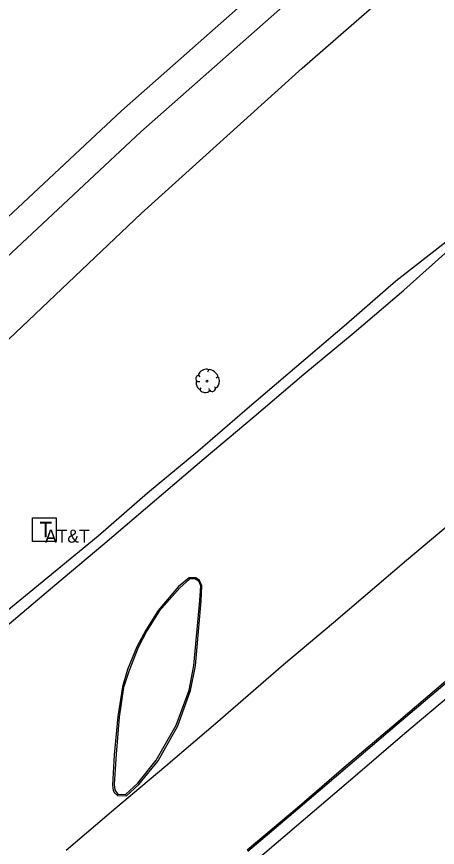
# Model space of a CAD drawing. Extents: x 1042086 to 1119166, y 1916606 to 1927565.
# Drawn here: x 1043115.4 to 1043276.4, y 1926533.5 to 1926851.6 of the extents above; entities that cross this region are included whole.
import ezdxf

# ---------------------------------------------------------------- set-up
doc = ezdxf.new("R2010")
doc.units = 0
for name, color, linetype in [('R_No Plot', 7, 'Continuous'), ('S_CURB', 7, 'Continuous'), ('S_EDGE_CONCRETE', 7, 'Continuous'), ('S_EDGE_PAVEMENT', 7, 'Continuous'), ('S_SHOULDER', 7, 'Continuous'), ('S_SIDEWALK', 7, 'Continuous'), ('S_TELEPHONE_UTILITIES', 7, 'Continuous'), ('S_TELEPHONE_UTILITIES_ANNOT', 7, 'Continuous'), ('S_TREE', 7, 'Continuous')]:
    doc.layers.add(name, color=color, linetype=linetype)

msp = doc.modelspace()

# ---------------------------------------------------------------- linework, layer by layer
at = {"layer": 'R_No Plot'}
for points in [[(1044190.35, 1927564.54), (1043981.84, 1927438.75), (1043847.5, 1927351.11), (1043782.09, 1927308.44), (1043697.07, 1927249.19), (1043570.31, 1927157.92), (1043487.46, 1927093.8), (1043395.3, 1927021.04), (1043346.81, 1926980.95), (1043282.61, 1926927.86), (1043155.48, 1926815.57), (1043010.71, 1926680.15), (1042651.83, 1926335.68), (1042368.92, 1926064.14), (1042086.02, 1925792.6)], [(1044196.03, 1927555.13), (1043987.69, 1927429.43), (1043853.51, 1927341.9), (1043788.24, 1927299.32), (1043703.43, 1927240.21), (1043576.89, 1927149.1), (1043494.23, 1927085.13), (1043402.21, 1927012.49), (1043353.82, 1926972.48), (1043289.76, 1926919.5), (1043162.88, 1926807.43), (1043018.28, 1926672.16), (1042659.44, 1926327.74), (1042376.54, 1926056.21), (1042093.64, 1925784.67)], [(1042478.4, 1926119.04), (1042593.51, 1926230.8), (1042805.67, 1926436.78), (1043162.99, 1926776.23), (1043224.64, 1926831.91), (1043251.28, 1926855.08), (1043316.64, 1926911.14), (1043414.38, 1926992.32), (1043498.45, 1927058.67), (1043606.9, 1927141.54), (1043742.89, 1927238.47), (1043809.93, 1927284.87), (1043730.4, 1927218.11), (1043687.56, 1927181.41)]]:
    msp.add_lwpolyline(points, dxfattribs=at)
at = {"layer": 'S_CURB'}
msp.add_lwpolyline([(1043203.91, 1926532.06), (1043222.97, 1926548.25), (1043242.02, 1926564.43), (1043261.02, 1926580.68), (1043280.9, 1926597.45), (1043299.84, 1926613.77), (1043313.23, 1926625.02), (1043315.83, 1926627.5), (1043317.07, 1926628.88), (1043319.73, 1926653.81), (1043320.19, 1926657.43), (1043321.03, 1926661.98), (1043324.28, 1926666.15)], dxfattribs=at)
msp.add_lwpolyline([(1043154.15, 1926553.83), (1043156.99, 1926553.69), (1043161.69, 1926558.01), (1043168.83, 1926566.88), (1043176.36, 1926580.23), (1043181.35, 1926593.72), (1043183.17, 1926603.09), (1043185.49, 1926627.97), (1043185.83, 1926633.66), (1043185.06, 1926635.38), (1043183.61, 1926636.35), (1043181.54, 1926636.17), (1043177.81, 1926632.9), (1043169.97, 1926623.94), (1043165.24, 1926616.36), (1043161.85, 1926610), (1043158.38, 1926601.22), (1043156.32, 1926594.67), (1043154.58, 1926583.34), (1043153.52, 1926569.12), (1043152.66, 1926557.67), (1043152.96, 1926555.49), (1043153.54, 1926554.55)], close=True, dxfattribs=at)
at = {"layer": 'S_EDGE_CONCRETE'}
msp.add_lwpolyline([(1042911.59, 1926420.57), (1042897.9, 1926435.96), (1042900.77, 1926438.95), (1042919.78, 1926455.34), (1042939.53, 1926471.89), (1042958.48, 1926488.19), (1042977.65, 1926504.25), (1042996.58, 1926520.57), (1043015.53, 1926536.87), (1043034.78, 1926552.83), (1043053.68, 1926569.19), (1043072.77, 1926585.33), (1043091.84, 1926601.49), (1043110.9, 1926617.67), (1043129.98, 1926633.83), (1043149.08, 1926649.95), (1043168.09, 1926666.19), (1043187.12, 1926682.4), (1043206.26, 1926698.48), (1043225.26, 1926714.73), (1043244.49, 1926730.7), (1043263.56, 1926746.87), (1043281.72, 1926763.08)], dxfattribs=at)
msp.add_lwpolyline([(1043153.95, 1926553.39), (1043157.36, 1926553.28), (1043162.15, 1926557.52), (1043169.51, 1926566.66), (1043177.03, 1926580.02), (1043181.96, 1926593.53), (1043183.8, 1926603.04), (1043185.93, 1926627.94), (1043186.27, 1926633.62), (1043185.37, 1926635.72), (1043183.97, 1926636.75), (1043181.45, 1926636.7), (1043177.31, 1926633.37), (1043169.49, 1926624.24), (1043164.75, 1926616.67), (1043161.33, 1926610.32), (1043157.86, 1926601.54), (1043155.93, 1926594.92), (1043154.1, 1926583.64), (1043152.74, 1926568.9), (1043152.03, 1926557.48), (1043152.25, 1926555.29), (1043152.81, 1926554.34)], close=True, dxfattribs=at)
at = {"layer": 'S_EDGE_PAVEMENT'}
for points in [[(1043134.32, 1926532.4), (1043153.39, 1926548.56), (1043172.45, 1926564.73), (1043191.46, 1926580.98), (1043217.47, 1926603.49), (1043236.61, 1926619.59), (1043264.57, 1926643.47), (1043283.75, 1926659.52), (1043285.33, 1926662.23), (1043291.48, 1926670.09), (1043297.24, 1926678.97), (1043302.57, 1926690.78), (1043306.08, 1926702.45), (1043308.51, 1926714.7), (1043310.31, 1926727.88), (1043312.83, 1926752.76), (1043313.2, 1926757.62)], [(1043203.53, 1926532.51), (1043222.69, 1926548.57), (1043241.6, 1926564.93), (1043260.67, 1926581.1), (1043280.46, 1926597.97), (1043299.5, 1926614.17), (1043312.64, 1926625.13), (1043315.29, 1926627.6), (1043316.5, 1926628.99), (1043319.12, 1926653.92), (1043319.48, 1926657.56), (1043320.51, 1926662.56), (1043323.81, 1926666.68), (1043323.75, 1926667.62)]]:
    msp.add_lwpolyline(points, dxfattribs=at)
at = {"layer": 'S_SHOULDER'}
msp.add_lwpolyline([(1042898.35, 1926441.3), (1042916.65, 1926458.38), (1042936.71, 1926475.14), (1042955.64, 1926491.46), (1042974.65, 1926507.71), (1042994.08, 1926523.45), (1043013.1, 1926539.67), (1043032.23, 1926555.77), (1043051, 1926572.28), (1043069.8, 1926588.75), (1043089.02, 1926604.75), (1043107.89, 1926621.14), (1043127.31, 1926636.9), (1043146.59, 1926652.82), (1043165.47, 1926669.21), (1043184.66, 1926685.24), (1043203.58, 1926701.57), (1043222.63, 1926717.76), (1043241.64, 1926733.98), (1043260.43, 1926750.48), (1043279.67, 1926765.43), (1043290.38, 1926775.16)], dxfattribs=at)
at = {"layer": 'S_SIDEWALK'}
msp.add_lwpolyline([(1043206.87, 1926528.51), (1043225.94, 1926544.68), (1043244.93, 1926560.94), (1043263.92, 1926577.21), (1043283.82, 1926593.93), (1043302.81, 1926610.2), (1043318.87, 1926623.94), (1043321.48, 1926626.42), (1043321.95, 1926627.95), (1043324.25, 1926652.94), (1043324.82, 1926656.54), (1043324.91, 1926657.57), (1043320.19, 1926657.43)], dxfattribs=at)
at = {"layer": 'S_TELEPHONE_UTILITIES'}
msp.add_lwpolyline([(1043121.5, 1926650.65), (1043121.5, 1926659.65), (1043130.5, 1926659.65), (1043130.5, 1926650.65)], close=True, dxfattribs=at)
at = {"layer": 'S_TREE'}
for p, q in [((1043184.97, 1926714.25), (1043185.48, 1926713.67)), ((1043188.77, 1926716.27), (1043188.38, 1926715.42)), ((1043192.34, 1926713.48), (1043191.68, 1926713.21)), ((1043184.31, 1926711.93), (1043185.44, 1926711.93)), ((1043185.48, 1926708.75), (1043185.94, 1926709.45)), ((1043189.16, 1926708.48), (1043189.08, 1926709.26)), ((1043191.56, 1926709.37), (1043191.1, 1926709.8))]:
    msp.add_line(p, q, dxfattribs=at)
msp.add_circle((1043188.21, 1926712.02), 0.341, dxfattribs=at)
for centre, major_axis, ratio, start_param, end_param in [((1043186.88, 1926715.23), (1.86, 1.08), 0.471018, 0, 3.141593), ((1043190.53, 1926714.9), (-1.81, 1.36), 0.405113, 3.141593, 6.283186), ((1043184.64, 1926713.11), (0.31, 1.03), 0.646762, 0, 3.141593), ((1043191.89, 1926711.49), (0.46, 2.04), 0.482994, 3.141593, 6.283185), ((1043184.95, 1926710.46), (-0.61, 1.6), 0.420543, 6.283185, 9.424777), ((1043187.41, 1926708.68), (-1.83, 0.19), 0.529943, 0, 3.141593), ((1043190.36, 1926708.97), (1.09, 0.46), 0.711534, 3.141592, 6.283185)]:
    msp.add_ellipse(centre, major_axis=major_axis, ratio=ratio, start_param=start_param, end_param=end_param, dxfattribs=at)

# ---------------------------------------------------------------- texts
at = {"layer": 'S_TELEPHONE_UTILITIES'}
msp.add_text('T', height=6, rotation=360, dxfattribs=at).set_placement((1043124.07, 1926652.15))
at = {"layer": 'S_TELEPHONE_UTILITIES_ANNOT'}
msp.add_text('AT&T', height=5, dxfattribs=at).set_placement((1043126.23, 1926650.17))

doc.saveas('drawing.dxf')
